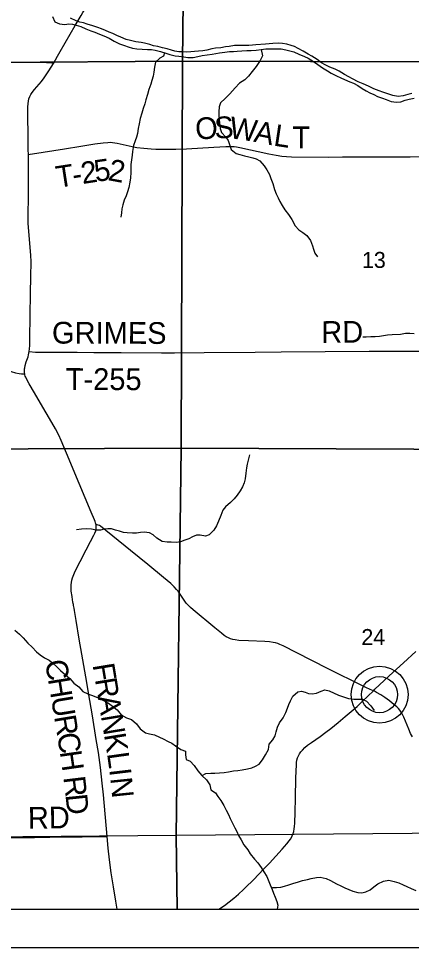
# Model space of a CAD drawing. Extents: x 0 to 70.2, y 0 to 31.4.
# Drawn here: x 3.272 to 4.299, y 14 to 16.429 of the extents above; entities that cross this region are included whole.
import ezdxf

# ---------------------------------------------------------------- set-up
doc = ezdxf.new("R2010")
doc.units = 0
for name, color, linetype in [('GM_X_County_Road', 7, 'Continuous'), ('GM_X_County_Road_Text', 7, 'Continuous'), ('GM_X_Major_River', 7, 'Continuous'), ('GM_X_Minor_River', 7, 'Continuous'), ('GM_X_Section', 7, 'Continuous'), ('GM_X_Section_Text', 7, 'Continuous'), ('GM_X_State_Route', 7, 'Continuous'), ('GM_X_Township_Road', 7, 'Continuous'), ('GM_X_Township_Road_Text', 7, 'Continuous'), ('GM_X_Unincorporated', 7, 'Continuous'), ('GM_X_Unincorporated_Location', 7, 'Continuous'), ('SH_Cut_Line', 7, 'Continuous'), ('SH_Data', 7, 'Continuous')]:
    doc.layers.add(name, color=color, linetype=linetype)

msp = doc.modelspace()

# ---------------------------------------------------------------- linework, layer by layer
at = {"layer": 'GM_X_County_Road'}
msp.add_line((3.363, 16.3114), (3.3737, 16.3305), dxfattribs=at)
for points in [[(3.3737, 16.3305), (3.3806, 16.3427), (3.4193, 16.4101), (3.4352, 16.4367), (3.4399, 16.4448), (3.4453, 16.4526), (3.4512, 16.4596), (3.4576, 16.4661), (3.4644, 16.4728), (3.4723, 16.4794), (3.4807, 16.4854), (3.4853, 16.4891)], [(3.2971, 16.0731), (3.2969, 16.0851), (3.2966, 16.1162), (3.2956, 16.1815), (3.2957, 16.1971), (3.2964, 16.2064), (3.2973, 16.2127), (3.2988, 16.2187), (3.301, 16.2247), (3.3038, 16.2303), (3.3072, 16.2356), (3.3129, 16.2431), (3.3313, 16.2641), (3.3387, 16.274), (3.3509, 16.2919), (3.363, 16.3114)], [(3.2993, 15.5577), (3.3003, 15.5655), (3.3008, 15.5738), (3.3013, 15.5923), (3.3028, 15.7104), (3.3038, 15.7534), (3.3041, 15.7936), (3.3037, 15.8091), (3.3022, 15.8308), (3.297, 15.8927), (3.2965, 15.9051), (3.2967, 15.9237), (3.2976, 15.9547), (3.2979, 15.9858), (3.2976, 16.0448), (3.2971, 16.0731)], [(3.2876, 15.5), (3.2872, 15.5031), (3.2869, 15.5063), (3.2869, 15.5094), (3.2871, 15.5126), (3.2876, 15.5157), (3.2889, 15.5219), (3.2918, 15.5309), (3.2963, 15.5445), (3.2977, 15.5498), (3.2985, 15.5537), (3.2993, 15.5577)], [(3.4742, 15.1049), (3.474, 15.1063), (3.4736, 15.1077), (3.4728, 15.1105), (3.4719, 15.1133), (3.4699, 15.1184), (3.4612, 15.1384), (3.4146, 15.2502), (3.4036, 15.276), (3.3831, 15.3257), (3.3766, 15.3395), (3.368, 15.3561), (3.3527, 15.3831), (3.3354, 15.4126), (3.3129, 15.45), (3.2994, 15.4735), (3.293, 15.4852), (3.2903, 15.4908), (3.2892, 15.4938), (3.2883, 15.4969), (3.2876, 15.5)], [(3.5035, 14.2898), (3.4933, 14.399), (3.4903, 14.4294), (3.4861, 14.4705), (3.4802, 14.5099), (3.4747, 14.5437), (3.4647, 14.6052), (3.4544, 14.6654), (3.4499, 14.6924), (3.4372, 14.7666), (3.43, 14.8064), (3.4221, 14.855), (3.4179, 14.8808), (3.4167, 14.887), (3.4159, 14.8909), (3.4153, 14.8942), (3.4148, 14.8966), (3.4144, 14.8996), (3.4137, 14.9036), (3.4129, 14.9087), (3.4116, 14.9172), (3.4095, 14.9314), (3.4092, 14.9416), (3.4094, 14.9479), (3.4101, 14.9541), (3.4113, 14.9602), (3.413, 14.9662), (3.4161, 14.9751), (3.4198, 14.9838), (3.4323, 15.0091), (3.4482, 15.0393), (3.46, 15.0612), (3.4687, 15.0776), (3.4713, 15.0832), (3.4734, 15.0889), (3.4741, 15.0918), (3.4746, 15.0948), (3.4747, 15.0962), (3.4748, 15.0981), (3.4747, 15.1012), (3.4745, 15.1032), (3.4742, 15.1049)], [(2.6808, 14.2841), (2.7074, 14.284), (2.8316, 14.2843), (2.8596, 14.2845), (2.8938, 14.2851), (2.9622, 14.2854), (3.0399, 14.2868), (3.1021, 14.2871), (3.1736, 14.2876), (3.2356, 14.2872), (3.3133, 14.2878), (3.3941, 14.289), (3.4376, 14.2895), (3.4749, 14.2901), (3.4936, 14.2899), (3.5035, 14.2898)], [(3.5295, 14.1), (3.5258, 14.1213), (3.5195, 14.1581), (3.514, 14.195), (3.5096, 14.229), (3.5063, 14.2599), (3.5035, 14.2898)]]:
    msp.add_lwpolyline(points, dxfattribs=at)
at = {"layer": 'GM_X_Major_River'}
for points in [[(3.3604, 16.4336), (3.3668, 16.42), (3.3789, 16.4147), (3.3922, 16.4135), (3.4032, 16.4147), (3.4127, 16.4139), (3.4225, 16.4116), (3.4343, 16.4075), (3.4475, 16.4014), (3.4604, 16.3965), (3.4707, 16.3934), (3.4832, 16.3881), (3.4949, 16.3836), (3.5082, 16.3771), (3.5214, 16.3695), (3.5355, 16.3623), (3.5487, 16.3578), (3.5586, 16.3544), (3.5692, 16.3513), (3.5813, 16.3494), (3.595, 16.3483), (3.609, 16.3479), (3.6192, 16.3476), (3.6287, 16.3457), (3.6431, 16.3422), (3.6568, 16.3385), (3.667, 16.335), (3.681, 16.3316), (3.6905, 16.3305), (3.7038, 16.3282), (3.7144, 16.3271), (3.728, 16.3271), (3.7405, 16.3297), (3.7519, 16.332), (3.7652, 16.3339), (3.7777, 16.3358), (3.7879, 16.3377), (3.7974, 16.3389), (3.8107, 16.3407), (3.8236, 16.3423), (3.8334, 16.3426), (3.8436, 16.3434), (3.8558, 16.3442), (3.8687, 16.3449), (3.88, 16.3453), (3.8929, 16.3461), (3.9062, 16.3476), (3.918, 16.3491), (3.9452, 16.3499), (3.9585, 16.3491), (3.9703, 16.3472), (3.9809, 16.3446), (3.9919, 16.3412), (4.0044, 16.3358), (4.0192, 16.3294), (4.029, 16.3248), (4.0434, 16.3161), (4.054, 16.3089), (4.0665, 16.3002), (4.0798, 16.2919), (4.0896, 16.2862), (4.1029, 16.2793), (4.1147, 16.274), (4.1241, 16.2691), (4.1378, 16.2634), (4.1476, 16.26), (4.1594, 16.2532), (4.1707, 16.246), (4.181, 16.2399), (4.1908, 16.2346), (4.2007, 16.2297), (4.2105, 16.2251), (4.2234, 16.2206), (4.2333, 16.2171), (4.2465, 16.2122), (4.2598, 16.2096), (4.2712, 16.2111), (4.2829, 16.2149), (4.2936, 16.2183), (4.3068, 16.2202)], [(4.3, 16.2327), (4.2901, 16.2301), (4.2776, 16.227), (4.2647, 16.2251), (4.2507, 16.2278), (4.2371, 16.2319), (4.2246, 16.2361), (4.2147, 16.2395), (4.2011, 16.2448), (4.1867, 16.2517), (4.1734, 16.2577), (4.1601, 16.263), (4.1454, 16.2706), (4.1359, 16.2763), (4.1245, 16.282), (4.1101, 16.2911), (4.0999, 16.296), (4.0859, 16.3017), (4.0737, 16.3074), (4.0643, 16.3131), (4.0525, 16.3218), (4.0389, 16.3305), (4.0294, 16.3358), (4.0161, 16.3434), (4.0032, 16.3506), (3.9938, 16.3552), (3.9843, 16.3586), (3.9737, 16.3616), (3.9616, 16.3635), (3.9513, 16.3639), (3.9369, 16.3631), (3.9274, 16.3624), (3.9172, 16.3616), (3.8926, 16.3597), (3.8831, 16.359), (3.8736, 16.3586), (3.8615, 16.3582), (3.8463, 16.3586), (3.8368, 16.3578), (3.8224, 16.3559), (3.8129, 16.3548), (3.8004, 16.3525), (3.7868, 16.351), (3.7773, 16.3495), (3.7637, 16.3464), (3.7538, 16.3445), (3.7421, 16.343), (3.7314, 16.3423), (3.722, 16.3415), (3.7121, 16.3411), (3.7019, 16.3415), (3.6909, 16.3419), (3.6806, 16.3434), (3.6712, 16.3457), (3.6602, 16.3491), (3.6484, 16.3525), (3.6359, 16.3555), (3.6245, 16.3574), (3.6151, 16.3604), (3.6014, 16.3639), (3.592, 16.3658), (3.5787, 16.368), (3.5647, 16.3711), (3.5533, 16.3741), (3.5389, 16.3798), (3.5287, 16.3843), (3.5177, 16.3896), (3.5082, 16.3934), (3.4987, 16.3976), (3.4881, 16.4018), (3.4786, 16.4052), (3.4657, 16.4094), (3.4513, 16.4139), (3.4411, 16.4173), (3.4316, 16.4196), (3.4218, 16.4226), (3.4078, 16.4295)]]:
    msp.add_lwpolyline(points, dxfattribs=at)
at = {"layer": 'GM_X_Minor_River'}
for points in [[(3.9064, 16.3476), (3.91, 16.3313), (3.9032, 16.3188), (3.8929, 16.3032), (3.883, 16.2903), (3.8732, 16.2778), (3.8633, 16.2683), (3.8497, 16.26), (3.8383, 16.2478), (3.8246, 16.2319), (3.8117, 16.2198), (3.8, 16.2087), (3.7966, 16.1974), (3.7958, 16.1845), (3.7954, 16.175), (3.7966, 16.1651), (3.7973, 16.1549), (3.7992, 16.1412), (3.8026, 16.1306), (3.8136, 16.1189), (3.82, 16.1094), (3.8231, 16.0991), (3.8276, 16.0859), (3.8405, 16.076), (3.8503, 16.073), (3.8628, 16.0696), (3.8735, 16.0673), (3.8841, 16.0642), (3.8935, 16.0616), (3.903, 16.0563), (3.9144, 16.0438), (3.9212, 16.0328), (3.9276, 16.0206), (3.9318, 16.0108), (3.9367, 15.9971), (3.9413, 15.9816), (3.9454, 15.9702), (3.9507, 15.9599), (3.9553, 15.9505), (3.9613, 15.9395), (3.9685, 15.9285), (3.9776, 15.9163), (3.986, 15.9031), (3.9947, 15.8867), (4.0049, 15.8761), (4.0155, 15.8689), (4.0257, 15.8613), (4.0352, 15.8484), (4.0401, 15.8348), (4.0435, 15.8253), (4.0469, 15.8154), (4.0538, 15.806)], [(3.6535, 16.3394), (3.6507, 16.3305), (3.6412, 16.3248), (3.6295, 16.3142), (3.6272, 16.3013), (3.6257, 16.2888), (3.6238, 16.2781), (3.6203, 16.2664), (3.6173, 16.2569), (3.6127, 16.2432), (3.6086, 16.2303), (3.6044, 16.2159), (3.6017, 16.2057), (3.5979, 16.1936), (3.5938, 16.181), (3.5896, 16.167), (3.5869, 16.1533), (3.5843, 16.1408), (3.5827, 16.1279), (3.5801, 16.1184), (3.5763, 16.1086), (3.5721, 16.0968), (3.5694, 16.0813), (3.5683, 16.0714), (3.5668, 16.0589), (3.5656, 16.0471), (3.5652, 16.0361), (3.5652, 16.0259), (3.5645, 16.0126), (3.563, 16.0009), (3.5599, 15.9872), (3.5569, 15.9758), (3.5527, 15.9652), (3.5481, 15.9538), (3.5444, 15.9413), (3.5421, 15.9307), (3.5405, 15.9208), (3.5387, 15.9091)], [(4.3064, 15.6047), (4.2947, 15.6055), (4.2837, 15.6049), (4.2704, 15.6027), (4.2492, 15.6021), (4.2366, 15.6007), (4.2264, 15.5989), (4.2154, 15.5971), (4.2044, 15.5961), (4.1934, 15.5962), (4.1812, 15.5959), (4.1718, 15.5956)], [(3.8753, 15.2882), (3.8696, 15.2635), (3.8674, 15.2541), (3.8662, 15.2404), (3.8639, 15.2256), (3.8613, 15.2146), (3.8575, 15.2044), (3.851, 15.1934), (3.8431, 15.1824), (3.8355, 15.1729), (3.826, 15.1634), (3.8131, 15.1524), (3.8063, 15.1429), (3.8006, 15.1293), (3.7949, 15.1148), (3.7896, 15.1019), (3.7827, 15.0913), (3.7702, 15.0792), (3.7604, 15.0754), (3.7463, 15.0777), (3.7369, 15.078), (3.7262, 15.0731), (3.7168, 15.0686), (3.7069, 15.0644), (3.6952, 15.0606), (3.6849, 15.0591), (3.6705, 15.0598), (3.6599, 15.0595), (3.6474, 15.0617), (3.6334, 15.0701), (3.6239, 15.0788), (3.6144, 15.0841), (3.6004, 15.086), (3.5905, 15.0849), (3.5803, 15.0833), (3.5697, 15.083), (3.5557, 15.0837), (3.5458, 15.0852), (3.5352, 15.0883), (3.5253, 15.0909), (3.5147, 15.0943), (3.5053, 15.0947), (3.4958, 15.0932), (3.4863, 15.0909), (3.4749, 15.0909), (3.4624, 15.0936), (3.4495, 15.0943), (3.4363, 15.0939), (3.4234, 15.0917)], [(3.2621, 14.8295), (3.2739, 14.8189), (3.2837, 14.8094), (3.2962, 14.7954), (3.3072, 14.7852)], [(3.3072, 14.7852), (3.3186, 14.773), (3.3281, 14.7651), (3.3391, 14.7575), (3.3512, 14.7507), (3.361, 14.7431), (3.3713, 14.7332), (3.3811, 14.7237), (3.3944, 14.7131), (3.4057, 14.7029), (3.4163, 14.6911), (3.4289, 14.6813), (3.4398, 14.6695), (3.4523, 14.6631), (3.4694, 14.657), (3.4838, 14.6509), (3.4955, 14.6445), (3.5065, 14.6384), (3.5175, 14.6312), (3.5297, 14.621), (3.5395, 14.6085), (3.5543, 14.6001), (3.5668, 14.5956), (3.5804, 14.5849), (3.5895, 14.5717), (3.6032, 14.5607), (3.6138, 14.5584), (3.6274, 14.5557), (3.6399, 14.5497), (3.6494, 14.5451), (3.663, 14.5383), (3.6725, 14.5341), (3.6824, 14.5273), (3.6956, 14.5178), (3.7081, 14.5133), (3.7081, 14.5034), (3.7104, 14.4917), (3.7203, 14.4871), (3.7309, 14.4753), (3.7407, 14.4617), (3.7509, 14.4499), (3.7631, 14.4378), (3.7718, 14.4253), (3.7748, 14.4124), (3.7866, 14.4044), (3.793, 14.3946), (3.8006, 14.3839), (3.8085, 14.3707), (3.8142, 14.3589), (3.8203, 14.3479), (3.8248, 14.3373), (3.8369, 14.313), (3.8422, 14.3028), (3.8472, 14.2925), (3.8536, 14.2812), (3.8612, 14.2683), (3.871, 14.255), (3.8778, 14.2451), (3.8888, 14.2311), (3.8972, 14.2216), (3.9059, 14.2087), (3.9131, 14.1973), (3.921, 14.1852), (3.9301, 14.164), (3.935, 14.1515), (3.9384, 14.1416), (3.9426, 14.1317), (3.9475, 14.12), (3.9498, 14.1101), (3.9483, 14.1)], [(3.7517, 14.4492), (3.7616, 14.4549), (3.7745, 14.4556), (3.7851, 14.456), (3.7976, 14.4568), (3.8097, 14.4575), (3.8207, 14.459), (3.8336, 14.4613), (3.8453, 14.4628), (3.8563, 14.464), (3.8704, 14.467), (3.8821, 14.4697), (3.8916, 14.4735), (3.9011, 14.4795), (3.9098, 14.4909), (3.9174, 14.5034), (3.925, 14.5179), (3.9269, 14.5315), (3.9367, 14.5425), (3.9424, 14.5535), (3.9458, 14.5641), (3.9485, 14.5755), (3.9542, 14.5869), (3.9633, 14.6005), (3.9705, 14.6138), (3.9751, 14.6256), (3.9785, 14.6351), (3.983, 14.6445), (3.9891, 14.6571), (4.002, 14.6681), (4.0115, 14.6696), (4.021, 14.6673), (4.0304, 14.6643), (4.0399, 14.6631), (4.0505, 14.6647), (4.0627, 14.6703), (4.0725, 14.6738), (4.0839, 14.6711), (4.1089, 14.6597), (4.1214, 14.6552), (4.1347, 14.651), (4.1483, 14.6491), (4.1586, 14.6495), (4.1711, 14.6487), (4.1813, 14.6438), (4.193, 14.6317), (4.2021, 14.6192)], [(3.9337, 14.1548), (3.9369, 14.1564), (3.9464, 14.1571), (3.9574, 14.1579), (3.9676, 14.1602), (3.9786, 14.1636), (3.9889, 14.167), (4.0036, 14.1716), (4.0146, 14.175), (4.0272, 14.1776), (4.0366, 14.1799), (4.0507, 14.183), (4.0601, 14.1833), (4.0761, 14.1799), (4.0878, 14.175), (4.1033, 14.1666), (4.1143, 14.1613), (4.1249, 14.156), (4.1356, 14.1515), (4.1462, 14.1473), (4.1591, 14.1439), (4.1693, 14.1431), (4.1799, 14.145), (4.1909, 14.1504), (4.2011, 14.1587), (4.211, 14.1663), (4.2262, 14.1735), (4.2402, 14.1758), (4.2542, 14.1727), (4.2663, 14.1689), (4.2773, 14.1636), (4.2876, 14.1595), (4.2982, 14.1542), (4.3107, 14.1489)]]:
    msp.add_lwpolyline(points, dxfattribs=at)
at = {"layer": 'GM_X_Section'}
for points in [[(2.7039, 17.3191), (3.7116, 17.3342), (3.7004, 16.3169), (2.7071, 16.3105)], [(3.7116, 17.3342), (4.7109, 17.3315), (4.7073, 16.3287), (4.7058, 16.315), (3.7004, 16.3169)], [(2.7071, 16.3105), (3.7004, 16.3169), (3.6966, 15.3051), (2.695, 15.3009), (2.7094, 15.8251)], [(3.7004, 16.3169), (4.7058, 16.315), (4.7107, 15.313), (4.7107, 15.3013), (3.6966, 15.3051)], [(3.6966, 15.3051), (3.6837, 14.2925), (2.681, 14.2838), (2.695, 15.3009)], [(3.6966, 15.3051), (4.7107, 15.3013), (4.7126, 14.3016), (3.6837, 14.2925)]]:
    msp.add_lwpolyline(points, close=True, dxfattribs=at)
at = {"layer": 'GM_X_Section_Text'}
msp.add_lwpolyline([(2.683, 14.1), (6.7623, 14.1)], dxfattribs=at)
at = {"layer": 'GM_X_State_Route'}
for points in [[(3.8644, 14.156), (3.8866, 14.178), (3.9127, 14.2046), (3.9277, 14.2204), (3.961, 14.2571), (3.9734, 14.2711), (3.9794, 14.2783), (3.983, 14.2834), (3.9863, 14.2888), (3.9876, 14.2916), (3.99, 14.2975), (3.9917, 14.3035), (3.9928, 14.3097), (3.9936, 14.3159), (3.9941, 14.3253), (3.9947, 14.3533), (3.9958, 14.3905), (3.9972, 14.4433), (3.9982, 14.4775), (3.9987, 14.4836), (3.9995, 14.4897), (4.0011, 14.4955), (4.0034, 14.5012), (4.0064, 14.5065), (4.0099, 14.5115), (4.0139, 14.5161), (4.0205, 14.5226), (4.0276, 14.5285), (4.0376, 14.5359), (4.0606, 14.5518), (4.0757, 14.5626), (4.0881, 14.572), (4.1075, 14.5877), (4.1262, 14.604), (4.157, 14.6302), (4.1707, 14.6428), (4.1997, 14.6709), (4.2038, 14.6749), (4.2515, 14.7193), (4.2605, 14.7278), (4.2788, 14.7444), (4.3111, 14.7734)], [(3.7955, 14.1), (3.8101, 14.1098), (3.8226, 14.119), (3.8348, 14.1287), (3.8465, 14.1389), (3.8601, 14.1517), (3.8644, 14.156)]]:
    msp.add_lwpolyline(points, dxfattribs=at)
for points in [[(2.6814, 14.1), (3.6862, 14.1), (3.6837, 14.2925), (2.681, 14.2838)], [(3.6862, 14.1), (4.7122, 14.1), (4.7126, 14.3016), (3.6837, 14.2925)]]:
    msp.add_lwpolyline(points, close=True, dxfattribs=at)
at = {"layer": 'GM_X_Township_Road'}
for points in [[(2.7068, 16.3127), (2.7169, 16.3128), (2.7945, 16.3133), (2.8314, 16.3136), (2.8625, 16.3138), (2.905, 16.3143), (2.9608, 16.3144), (3.0104, 16.3147), (3.0477, 16.3149), (3.1627, 16.3154), (3.2032, 16.3156), (3.238, 16.3151), (3.2654, 16.3147), (3.345, 16.314), (3.35, 16.3138), (3.3558, 16.3133), (3.363, 16.3114)], [(3.2971, 16.0731), (3.3021, 16.0738), (3.3083, 16.0747), (3.3913, 16.0878), (3.4342, 16.0949), (3.471, 16.1008), (3.4926, 16.1037), (3.5049, 16.1049), (3.511, 16.1051), (3.5172, 16.1048), (3.5233, 16.1041), (3.5294, 16.1031), (3.5534, 16.0975), (3.5685, 16.094), (3.5808, 16.0919), (3.5993, 16.0895), (3.618, 16.0876), (3.6304, 16.0869), (3.646, 16.0867), (3.6832, 16.0872), (3.7112, 16.0882), (3.7827, 16.0921), (3.8137, 16.0938), (3.8292, 16.0942), (3.8353, 16.0938), (3.8414, 16.093), (3.8506, 16.0914), (3.9266, 16.0752), (3.945, 16.0716), (3.9604, 16.0692), (3.9728, 16.0679), (3.9852, 16.0673), (4.0817, 16.0666), (4.119, 16.067), (4.1937, 16.0672), (4.2963, 16.0674), (4.3772, 16.0676)], [(3.2993, 15.5577), (3.3161, 15.5567), (3.3347, 15.5566), (3.4248, 15.5561), (3.4683, 15.5556), (3.5397, 15.5553), (3.6452, 15.5548), (3.6791, 15.5548), (3.7567, 15.5553), (3.8903, 15.5568), (3.9586, 15.5574), (4.1885, 15.5586), (4.2786, 15.5593), (4.3687, 15.5593)], [(3.133, 15.5257), (3.1474, 15.5253), (3.1878, 15.5252), (3.2002, 15.5249), (3.2063, 15.5243), (3.2124, 15.523), (3.2154, 15.5221), (3.221, 15.5196), (3.232, 15.5138), (3.2375, 15.5111), (3.252, 15.5058), (3.2639, 15.5023), (3.273, 15.5002), (3.2792, 15.4997), (3.2828, 15.4998), (3.2876, 15.5)], [(4.1997, 14.6709), (4.1915, 14.6744), (4.1803, 14.6798), (4.1469, 14.6963), (4.1078, 14.7153), (4.0799, 14.7292), (3.9998, 14.7703), (3.9636, 14.7884), (3.9552, 14.7922), (3.9495, 14.7944), (3.9436, 14.7962), (3.9376, 14.7974), (3.9284, 14.7988), (3.9161, 14.7997), (3.8726, 14.8017), (3.8477, 14.8029), (3.8384, 14.804), (3.8323, 14.8053), (3.8262, 14.8071), (3.8204, 14.8094), (3.8148, 14.8123), (3.8095, 14.8157), (3.802, 14.8214), (3.7852, 14.8352), (3.7279, 14.8831), (3.7209, 14.8892), (3.7164, 14.8936), (3.7101, 14.9005), (3.7045, 14.9081), (3.6926, 14.9263), (3.689, 14.9313), (3.6851, 14.9361), (3.6787, 14.9427), (3.6696, 14.9511), (3.6507, 14.9672), (3.6099, 15.0008), (3.5643, 15.0382), (3.4862, 15.1017), (3.483, 15.1033), (3.4801, 15.1043), (3.4774, 15.1047), (3.4742, 15.1049)], [(4.3023, 14.551), (4.2972, 14.5592), (4.2921, 14.5704), (4.2793, 14.6017), (4.2772, 14.6072), (4.2743, 14.6124), (4.2692, 14.62), (4.2654, 14.6248), (4.2612, 14.6292), (4.2493, 14.639), (4.242, 14.6447), (4.2293, 14.6536), (4.2189, 14.6604), (4.2083, 14.6668), (4.2029, 14.6696), (4.1997, 14.6709)]]:
    msp.add_lwpolyline(points, dxfattribs=at)
at = {"layer": 'GM_X_Unincorporated'}
for radius in [0.0744, 0.0472]:
    msp.add_circle((4.2159, 14.6609), radius, dxfattribs=at)
at = {"layer": 'GM_X_Unincorporated_Location'}
msp.add_line((4.2159, 14.6609), (4.2159, 14.6609), dxfattribs=at)
at = {"layer": 'SH_Cut_Line'}
msp.add_lwpolyline([(2.1, 20.9), (2.1, 14.1), (6.7623, 14.1)], dxfattribs=at)
at = {"layer": 'SH_Data'}
for p, q in [((2.1, 14.1), (8.9, 14.1)), ((2, 14), (9, 14))]:
    msp.add_line(p, q, dxfattribs=at)

# ---------------------------------------------------------------- texts
at = {"layer": 'GM_X_County_Road_Text'}
for s, height, rotation, p in [('C', 0.0568, 279.3379, (3.3405, 14.7482)), ('F', 0.0568, 279.3155, (3.4649, 14.7389)), ('H', 0.0568, 279.3378, (3.3481, 14.7021)), ('R', 0.0568, 279.3141, (3.4711, 14.7011)), ('U', 0.0568, 279.3378, (3.3562, 14.6528)), ('A', 0.0568, 279.312, (3.4786, 14.655)), ('R', 0.0568, 279.2949, (3.3643, 14.6035)), ('N', 0.0568, 279.3143, (3.4867, 14.6057)), ('C', 0.0568, 279.0138, (3.3719, 14.5575)), ('K', 0.0568, 279.2234, (3.4948, 14.5564)), ('H', 0.0568, 278.1801, (3.3791, 14.5116)), ('L', 0.0568, 277.9974, (3.5028, 14.5073)), ('I', 0.0568, 276.7203, (3.5086, 14.4656)), ('R', 0.0568, 276.8031, (3.3886, 14.4451)), ('N', 0.0568, 275.7835, (3.5113, 14.4426)), ('D', 0.0568, 275.8567, (3.3941, 14.399)), ('RD', 0.05682, 0.4936, (3.296, 14.3105))]:
    msp.add_text(s, height=height, rotation=rotation, dxfattribs=at).set_placement(p)
at = {"layer": 'GM_X_Section_Text'}
for s, p in [('13', (4.1699, 15.7766)), ('24', (4.1683, 14.7906))]:
    msp.add_text(s, height=0.04186, rotation=0, dxfattribs=at).set_placement(p)
at = {"layer": 'GM_X_Township_Road_Text'}
for s, height, rotation, p in [('O', 0.0568, 3.0469, (3.735, 16.1122)), ('S', 0.0568, 2.3193, (3.7847, 16.1148)), ('W', 0.0568, 351.693, (3.8202, 16.1165)), ('A', 0.0568, 348.5329, (3.8846, 16.1071)), ('L', 0.0568, 351.4206, (3.9366, 16.0966)), ('T', 0.0568, 0.1064, (3.988, 16.0896)), ('2', 0.0568, 8.7984, (3.4389, 15.9958)), ('5', 0.0568, 8.3244, (3.4733, 16.0012)), ('2', 0.0568, 349.6556, (3.5031, 16.0063)), ('T', 0.0568, 8.8289, (3.3738, 15.9857)), ('-', 0.0568, 8.8168, (3.4158, 15.9922)), ('GRIMES', 0.05682, 359.8174, (3.3588, 15.5789)), ('RD', 0.05682, 0.4937, (4.0635, 15.5805)), ('T-255', 0.05682, 359.7176, (3.3948, 15.4579))]:
    msp.add_text(s, height=height, rotation=rotation, dxfattribs=at).set_placement(p)

doc.saveas('drawing.dxf')
